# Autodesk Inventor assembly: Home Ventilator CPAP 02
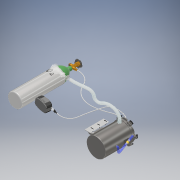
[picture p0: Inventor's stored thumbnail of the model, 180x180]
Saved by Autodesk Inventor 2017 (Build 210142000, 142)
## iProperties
Created: 2020-03
Part Number: Home Ventilator CPAP 02
Document SubType Name: Assembly
Designer: user
Author: user
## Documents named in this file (18)
- C:\Users\user\Documents\Inventor\Home Ventilator CPAP\Home Ventilator CPAP 02.iam
- C:\Users\user\Documents\Inventor\Home Ventilator CPAP\Water container 02.ipt
- C:\Users\user\Documents\Inventor\Home Ventilator CPAP\Rubber ring.ipt
- C:\Users\user\Documents\Inventor\Home Ventilator CPAP\Cap for container 02.ipt
- C:\Users\user\Documents\Inventor\Home Ventilator CPAP\Pipe conector.ipt
- C:\Users\user\Documents\Inventor\Home Ventilator CPAP\Toggle.ipt
- C:\Users\user\Documents\Inventor\Home Ventilator CPAP\Shaft.ipt
- C:\Users\user\Documents\Inventor\Home Ventilator CPAP\Oxygen hose.ipt
- C:\Users\user\Documents\Inventor\Home Ventilator CPAP\Oxygen bottle.ipt
- C:\Users\user\Documents\Inventor\Home Ventilator CPAP\Rib hose for mask.iam
- C:\Users\user\Documents\Inventor\Home Ventilator CPAP\Inline valve.ipt
- C:\Users\user\Documents\Inventor\Home Ventilator CPAP\air pump aquarium.ipt
- C:\Users\user\Documents\Inventor\Home Ventilator CPAP\Mask.iam
- C:\Users\user\Documents\Inventor\Home Ventilator CPAP\Air pump hose.ipt
- C:\Users\user\Documents\Inventor\Home Ventilator CPAP\Water in pot.ipt
- C:\Users\user\Documents\Inventor\Home Ventilator CPAP\Assem1.iam
- C:\Users\user\Documents\Inventor\Home Ventilator CPAP\Valve NEW.iam
- C:\Users\user\Documents\Inventor\Home Ventilator CPAP\Pipe for valve.ipt
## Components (28 placed, 17 different names)
1. Water container 02:1 — Mate:1, Mate:2, Mate:3, Mate:5, Mate:6, Mate:11, Mate:13, Mate:14, Mate:15, Mate:16, Mate:17, Mate:24, Mate:26, Mate:28, Mate:30, Mate:32, Mate:34, Flush:1, Mate:41, Mate:42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
2. Rubber ring:1 — Mate:2, Mate:3, Mate:4
3. Cap for container 02:1 — Mate:4, Mate:5, Mate:6, Mate:7, Mate:8, Mate:9, Mate:10, Mate:12, Mate:18, Mate:19, Mate:20, Mate:21, Mate:22, Mate:37, Mate:38, Mate:39, Mate:40
4. Pipe conector:1 — Mate:8, Mate:9, Mate:44, Mate:45
5. Pipe conector:2 — Mate:7, Mate:10, Mate:35
6. Toggle:1 — Mate:13, Mate:22, Mate:33, Mate:37
7. Toggle:2 — Mate:14, Mate:21, Mate:31, Mate:40
8. Toggle:3 — Mate:15, Mate:20, Mate:29
9. Toggle:4 — Mate:16, Mate:19, Mate:27, Mate:38
10. Toggle:5 — Mate:17, Mate:18, Mate:25, Mate:39
11. Toggle:6 — Mate:11, Mate:12, Mate:23
12. Shaft:1 — Mate:23, Mate:24
13. Shaft:2 — Mate:25, Mate:26
14. Shaft:3 — Mate:27, Mate:28
15. Shaft:4 — Mate:29, Mate:30
16. Shaft:5 — Mate:31, Mate:32
17. Shaft:6 — Mate:33, Mate:34
18. Oxygen hose:1 — Mate:35, Mate:36
19. Oxygen bottle:1 — Flush:1, Mate:36
20. Rib hose for mask:1 [sub-assembly] — Mate:41, Mate:42, Cylindrical:1
21. Inline valve:1 — Cylindrical:1, Mate:43
22. air pump aquarium:1 — Cylindrical:2
23. Mask:1 [sub-assembly] — Mate:43
24. Air pump hose:1 — Mate:44, Mate:45, Cylindrical:2
25. Water in pot:1 — Mate:46, Mate:47
26. Assem1:1 [sub-assembly] — Mate:48, Mate:49
27. Valve NEW:1 [sub-assembly] — Angle:1, Mate:53, Mate:54
28. Pipe for valve:1 — Mate:51, Mate:52, Mate:53, Mate:54
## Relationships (57: Mate 53, CylindricalJoint 2, Flush 1, Angle 1)
- Mate:1: Water container 02:1
- Mate:2: Water container 02:1 ↔ Rubber ring:1
- Mate:3: Water container 02:1 ↔ Rubber ring:1
- Mate:4: Rubber ring:1 ↔ Cap for container 02:1
- Mate:5: Water container 02:1 ↔ Cap for container 02:1
- Mate:6: Water container 02:1 ↔ Cap for container 02:1
- Mate:7: Cap for container 02:1 ↔ Pipe conector:2
- Mate:8: Cap for container 02:1 ↔ Pipe conector:1
- Mate:9: Cap for container 02:1 ↔ Pipe conector:1
- Mate:10: Cap for container 02:1 ↔ Pipe conector:2
- Mate:11: Water container 02:1 ↔ Toggle:6
- Mate:12: Cap for container 02:1 ↔ Toggle:6
- Mate:13: Water container 02:1 ↔ Toggle:1
- Mate:14: Water container 02:1 ↔ Toggle:2
- Mate:15: Water container 02:1 ↔ Toggle:3
- Mate:16: Water container 02:1 ↔ Toggle:4
- Mate:17: Water container 02:1 ↔ Toggle:5
- Mate:18: Cap for container 02:1 ↔ Toggle:5
- Mate:19: Cap for container 02:1 ↔ Toggle:4
- Mate:20: Cap for container 02:1 ↔ Toggle:3
- Mate:21: Cap for container 02:1 ↔ Toggle:2
- Mate:22: Cap for container 02:1 ↔ Toggle:1
- Mate:23: Toggle:6 ↔ Shaft:1
- Mate:24: Water container 02:1 ↔ Shaft:1
- Mate:25: Toggle:5 ↔ Shaft:2
- Mate:26: Water container 02:1 ↔ Shaft:2
- Mate:27: Toggle:4 ↔ Shaft:3
- Mate:28: Water container 02:1 ↔ Shaft:3
- Mate:29: Toggle:3 ↔ Shaft:4
- Mate:30: Water container 02:1 ↔ Shaft:4
- Mate:31: Toggle:2 ↔ Shaft:5
- Mate:32: Water container 02:1 ↔ Shaft:5
- Mate:33: Toggle:1 ↔ Shaft:6
- Mate:34: Water container 02:1 ↔ Shaft:6
- Mate:35: Pipe conector:2 ↔ Oxygen hose:1
- Flush:1: Water container 02:1 ↔ Oxygen bottle:1
- Mate:36: Oxygen hose:1 ↔ Oxygen bottle:1
- Mate:37: Cap for container 02:1 ↔ Toggle:1
- Mate:38: Cap for container 02:1 ↔ Toggle:4
- Mate:39: Cap for container 02:1 ↔ Toggle:5
- Mate:40: Cap for container 02:1 ↔ Toggle:2
- Mate:41: Water container 02:1 ↔ Rib hose for mask:1
- Mate:42: Water container 02:1 ↔ Rib hose for mask:1
- Cylindrical:1: Rib hose for mask:1 ↔ Inline valve:1
- Mate:43: Inline valve:1 ↔ Mask:1
- Mate:44: Pipe conector:1 ↔ Air pump hose:1
- Mate:45: Pipe conector:1 ↔ Air pump hose:1
- Cylindrical:2: air pump aquarium:1 ↔ Air pump hose:1
- Mate:46: Water container 02:1 ↔ Water in pot:1
- Mate:47: Water container 02:1 ↔ Water in pot:1
- Mate:48: Water container 02:1 ↔ Assem1:1
- Mate:49: Water container 02:1 ↔ Assem1:1
- Angle:1: Water container 02:1 ↔ Valve NEW:1
- Mate:51: Water container 02:1 ↔ Pipe for valve:1
- Mate:52: Water container 02:1 ↔ Pipe for valve:1
- Mate:53: Valve NEW:1 ↔ Pipe for valve:1
- Mate:54: Valve NEW:1 ↔ Pipe for valve:1
